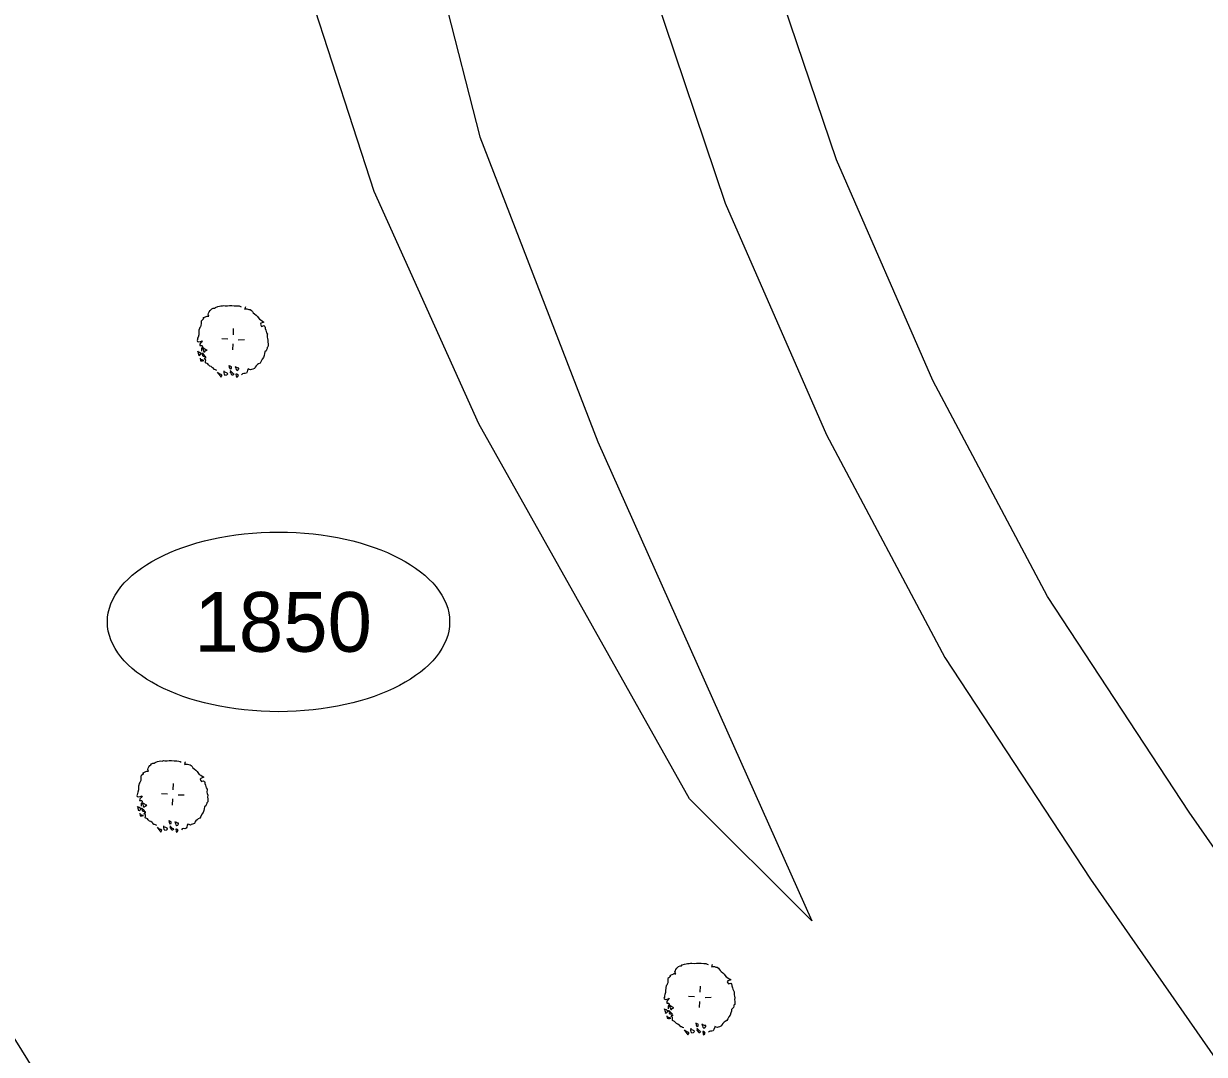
# Model space of a CAD drawing. Extents: x -601739 to -601442, y -1201912 to -1200862.
# Drawn here: x -601529.36 to -601489.81, y -1201669.33 to -1201634.81 of the extents above; entities that cross this region are included whole.
import ezdxf

# ---------------------------------------------------------------- set-up
doc = ezdxf.new("R2010")
doc.units = 0
for name, color, linetype in [('Hranice parcel', 7, 'Continuous'), ('Parcelní čísla', 7, 'Continuous'), ('u_dotčené parcely', 7, 'Continuous'), ('u_vysadba', 7, 'Continuous'), ('Vnitřní kresba', 7, 'Continuous')]:
    doc.layers.add(name, color=color, linetype=linetype)

msp = doc.modelspace()

# ---------------------------------------------------------------- linework, layer by layer
at = {"layer": 'Hranice parcel'}
for points in [[(-601518.5, -1201574.62), (-601510.22, -1201581.07), (-601510.94, -1201612.53), (-601510.72, -1201619.53), (-601510.05, -1201624.75), (-601508.24, -1201633.75), (-601505.86, -1201640.82), (-601502.47, -1201648.58), (-601498.5, -1201656.04), (-601493.62, -1201663.46), (-601488.75, -1201670.45), (-601479.72, -1201682.69), (-601465.426, -1201700.638)], [(-601505.676, -1201700.638), (-601519.73, -1201684.8), (-601540.64, -1201651.14), (-601563.05, -1201608.38), (-601567.44, -1201599.25)], [(-601460.43, -1201700.48), (-601476.54, -1201680.26), (-601485.5, -1201668.12), (-601490.31, -1201661.22), (-601495.06, -1201653.99), (-601498.9, -1201646.76), (-601502.13, -1201639.37), (-601504.35, -1201632.81), (-601505.66, -1201626.3)]]:
    msp.add_lwpolyline(points, dxfattribs=at)
at = {"layer": 'u_dotčené parcely'}
msp.add_ellipse((-601520.821, -1201654.846), major_axis=(-5.732, 0), ratio=0.524694, dxfattribs=at)
at = {"layer": 'u_vysadba'}
for points in [[(-601523.335, -1201644.685), (-601523.333, -1201644.656), (-601523.273, -1201644.63), (-601523.243, -1201644.617), (-601523.213, -1201644.604), (-601523.184, -1201644.605), (-601523.155, -1201644.607), (-601523.168, -1201644.577), (-601523.181, -1201644.547), (-601523.164, -1201644.504), (-601523.147, -1201644.461), (-601523.116, -1201644.418), (-601523.085, -1201644.391), (-601523.054, -1201644.363), (-601523.009, -1201644.336), (-601522.965, -1201644.338), (-601522.934, -1201644.311), (-601522.86, -1201644.285), (-601522.801, -1201644.274), (-601522.756, -1201644.262), (-601522.698, -1201644.265), (-601522.653, -1201644.252), (-601522.609, -1201644.255), (-601522.536, -1201644.259), (-601522.463, -1201644.248), (-601522.39, -1201644.252), (-601522.302, -1201644.256), (-601522.214, -1201644.261), (-601522.141, -1201644.265), (-601522.098, -1201644.282), (-601522.07, -1201644.298)], [(-601521.923, -1201644.291), (-601521.939, -1201644.319), (-601521.941, -1201644.349), (-601521.957, -1201644.377), (-601521.912, -1201644.365), (-601521.883, -1201644.366), (-601521.854, -1201644.368), (-601521.811, -1201644.385), (-601521.767, -1201644.387), (-601521.725, -1201644.419), (-601521.697, -1201644.449), (-601521.67, -1201644.495), (-601521.628, -1201644.526), (-601521.572, -1201644.573), (-601521.53, -1201644.619), (-601521.503, -1201644.65), (-601521.462, -1201644.711), (-601521.405, -1201644.743), (-601521.363, -1201644.775), (-601521.32, -1201644.791), (-601521.321, -1201644.821)], [(-601523.335, -1201644.685), (-601523.336, -1201644.7), (-601523.382, -1201644.741), (-601523.413, -1201644.769), (-601523.415, -1201644.813), (-601523.417, -1201644.856), (-601523.42, -1201644.915), (-601523.437, -1201644.958), (-601523.453, -1201644.986), (-601523.469, -1201645.015), (-601523.487, -1201645.072), (-601523.489, -1201645.102), (-601523.492, -1201645.16), (-601523.494, -1201645.204), (-601523.496, -1201645.233), (-601523.514, -1201645.305), (-601523.531, -1201645.348), (-601523.533, -1201645.392), (-601523.549, -1201645.42), (-601523.536, -1201645.45), (-601523.493, -1201645.467), (-601523.404, -1201645.443), (-601523.374, -1201645.43), (-601523.407, -1201645.487), (-601523.437, -1201645.514), (-601523.453, -1201645.543), (-601523.456, -1201645.586), (-601523.427, -1201645.588), (-601523.383, -1201645.59), (-601523.37, -1201645.62), (-601523.387, -1201645.663), (-601523.403, -1201645.692), (-601523.405, -1201645.736), (-601523.407, -1201645.779)], [(-601521.321, -1201644.821), (-601521.366, -1201644.833), (-601521.411, -1201644.845), (-601521.427, -1201644.874), (-601521.414, -1201644.904), (-601521.387, -1201644.949), (-601521.357, -1201644.936), (-601521.312, -1201644.924), (-601521.284, -1201644.954), (-601521.271, -1201644.984), (-601521.273, -1201645.014), (-601521.247, -1201645.074), (-601521.235, -1201645.118), (-601521.222, -1201645.163), (-601521.195, -1201645.208), (-601521.197, -1201645.237), (-601521.199, -1201645.281), (-601521.201, -1201645.31), (-601521.189, -1201645.355), (-601521.177, -1201645.414), (-601521.18, -1201645.472), (-601521.169, -1201645.532), (-601521.17, -1201645.561), (-601521.172, -1201645.59), (-601521.174, -1201645.634), (-601521.205, -1201645.661), (-601521.206, -1201645.691), (-601521.223, -1201645.734), (-601521.239, -1201645.762), (-601521.285, -1201645.804), (-601521.289, -1201645.862), (-601521.306, -1201645.92), (-601521.325, -1201645.992), (-601521.372, -1201646.048), (-601521.405, -1201646.119), (-601521.437, -1201646.176), (-601521.497, -1201646.202), (-601521.528, -1201646.23), (-601521.574, -1201646.272), (-601521.605, -1201646.314), (-601521.622, -1201646.357), (-601521.682, -1201646.383), (-601521.727, -1201646.395), (-601521.757, -1201646.408), (-601521.8, -1201646.391), (-601521.843, -1201646.375), (-601521.86, -1201646.418), (-601521.877, -1201646.475), (-601521.894, -1201646.518), (-601521.939, -1201646.531), (-601521.983, -1201646.528)], [(-601522.335, -1201645.227), (-601522.325, -1201645.022)], [(-601523.357, -1201645.65), (-601523.359, -1201645.694), (-601523.346, -1201645.724), (-601523.334, -1201645.769), (-601523.32, -1201645.799), (-601523.291, -1201645.8), (-601523.275, -1201645.772), (-601523.215, -1201645.746), (-601523.258, -1201645.729), (-601523.287, -1201645.713), (-601523.344, -1201645.68)], [(-601522.519, -1201645.378), (-601522.724, -1201645.367)], [(-601522.352, -1201645.533), (-601522.362, -1201645.738)], [(-601522.169, -1201645.396), (-601521.963, -1201645.393)], [(-601523.539, -1201645.772), (-601523.526, -1201645.802), (-601523.513, -1201645.847), (-601523.5, -1201645.877), (-601523.502, -1201645.906), (-601523.473, -1201645.922), (-601523.443, -1201645.895), (-601523.397, -1201645.853), (-601523.426, -1201645.852), (-601523.468, -1201645.82), (-601523.511, -1201645.803)], [(-601523.449, -1201646.011), (-601523.439, -1201646.1), (-601523.395, -1201646.102), (-601523.366, -1201646.104), (-601523.321, -1201646.091), (-601523.379, -1201646.074), (-601523.423, -1201646.071), (-601523.436, -1201646.041)], [(-601523.381, -1201645.839), (-601523.34, -1201645.885), (-601523.298, -1201645.932), (-601523.256, -1201645.963)], [(-601523.256, -1201645.963), (-601523.285, -1201645.962), (-601523.314, -1201645.96), (-601523.344, -1201645.958), (-601523.357, -1201645.929), (-601523.355, -1201645.899), (-601523.368, -1201645.869)], [(-601522.885, -1201646.422), (-601522.928, -1201646.405), (-601522.956, -1201646.389), (-601522.986, -1201646.387), (-601523.012, -1201646.342), (-601523.041, -1201646.326), (-601523.083, -1201646.294), (-601523.126, -1201646.277), (-601523.168, -1201646.231), (-601523.195, -1201646.201), (-601523.267, -1201646.168), (-601523.264, -1201646.124), (-601523.262, -1201646.08), (-601523.275, -1201646.05), (-601523.304, -1201646.034), (-601523.272, -1201645.992), (-601523.243, -1201645.993)], [(-601522.873, -1201646.481), (-601522.777, -1201646.603), (-601522.75, -1201646.649), (-601522.719, -1201646.606), (-601522.717, -1201646.577), (-601522.746, -1201646.561), (-601522.789, -1201646.544), (-601522.817, -1201646.528), (-601522.846, -1201646.512)], [(-601522.651, -1201646.434), (-601522.655, -1201646.507), (-601522.643, -1201646.552), (-601522.615, -1201646.583), (-601522.556, -1201646.571), (-601522.525, -1201646.543), (-601522.538, -1201646.514), (-601522.581, -1201646.497), (-601522.624, -1201646.48)], [(-601522.481, -1201646.253), (-601522.47, -1201646.327), (-601522.443, -1201646.372), (-601522.398, -1201646.36), (-601522.397, -1201646.331), (-601522.395, -1201646.301), (-601522.438, -1201646.285), (-601522.467, -1201646.268)], [(-601522.446, -1201646.431), (-601522.362, -1201646.508), (-601522.334, -1201646.524), (-601522.321, -1201646.554), (-601522.352, -1201646.582), (-601522.381, -1201646.58), (-601522.394, -1201646.55), (-601522.421, -1201646.505), (-601522.448, -1201646.474)], [(-601522.278, -1201646.293), (-601522.252, -1201646.353), (-601522.239, -1201646.398), (-601522.212, -1201646.428), (-601522.182, -1201646.415), (-601522.15, -1201646.373), (-601522.149, -1201646.344), (-601522.192, -1201646.341), (-601522.221, -1201646.325), (-601522.249, -1201646.309), (-601522.278, -1201646.308)], [(-601522.247, -1201646.544), (-601522.236, -1201646.617), (-601522.223, -1201646.647), (-601522.193, -1201646.634), (-601522.162, -1201646.592), (-601522.189, -1201646.561), (-601522.218, -1201646.545), (-601522.247, -1201646.544)], [(-601521.983, -1201646.528), (-601522.027, -1201646.541), (-601522.058, -1201646.568)], [(-601525.353, -1201659.926), (-601525.352, -1201659.897), (-601525.292, -1201659.871), (-601525.262, -1201659.858), (-601525.232, -1201659.845), (-601525.203, -1201659.847), (-601525.173, -1201659.848), (-601525.186, -1201659.818), (-601525.199, -1201659.788), (-601525.183, -1201659.745), (-601525.166, -1201659.702), (-601525.134, -1201659.66), (-601525.103, -1201659.632), (-601525.073, -1201659.605), (-601525.027, -1201659.578), (-601524.983, -1201659.58), (-601524.953, -1201659.552), (-601524.878, -1201659.527), (-601524.819, -1201659.515), (-601524.774, -1201659.503), (-601524.716, -1201659.506), (-601524.671, -1201659.494), (-601524.628, -1201659.496), (-601524.555, -1201659.5), (-601524.481, -1201659.489), (-601524.408, -1201659.493), (-601524.32, -1201659.498), (-601524.233, -1201659.502), (-601524.16, -1201659.506), (-601524.117, -1201659.523), (-601524.088, -1201659.539)], [(-601523.941, -1201659.532), (-601523.957, -1201659.561), (-601523.959, -1201659.59), (-601523.975, -1201659.619), (-601523.931, -1201659.606), (-601523.901, -1201659.608), (-601523.872, -1201659.609), (-601523.829, -1201659.626), (-601523.785, -1201659.629), (-601523.743, -1201659.66), (-601523.715, -1201659.691), (-601523.688, -1201659.736), (-601523.646, -1201659.768), (-601523.59, -1201659.815), (-601523.549, -1201659.861), (-601523.521, -1201659.891), (-601523.48, -1201659.952), (-601523.423, -1201659.984), (-601523.381, -1201660.016), (-601523.338, -1201660.033), (-601523.34, -1201660.062)], [(-601525.353, -1201659.926), (-601525.354, -1201659.941), (-601525.4, -1201659.983), (-601525.431, -1201660.01), (-601525.433, -1201660.054), (-601525.435, -1201660.098), (-601525.439, -1201660.156), (-601525.455, -1201660.199), (-601525.472, -1201660.228), (-601525.488, -1201660.256), (-601525.505, -1201660.314), (-601525.507, -1201660.343), (-601525.51, -1201660.401), (-601525.512, -1201660.445), (-601525.514, -1201660.474), (-601525.532, -1201660.547), (-601525.549, -1201660.59), (-601525.552, -1201660.633), (-601525.568, -1201660.662), (-601525.555, -1201660.692), (-601525.512, -1201660.709), (-601525.422, -1201660.684), (-601525.393, -1201660.671), (-601525.425, -1201660.728), (-601525.456, -1201660.756), (-601525.472, -1201660.784), (-601525.474, -1201660.828), (-601525.445, -1201660.829), (-601525.401, -1201660.832), (-601525.388, -1201660.862), (-601525.405, -1201660.905), (-601525.421, -1201660.933), (-601525.423, -1201660.977), (-601525.426, -1201661.021)], [(-601524.354, -1201660.468), (-601524.343, -1201660.264)], [(-601523.34, -1201660.062), (-601523.384, -1201660.074), (-601523.429, -1201660.087), (-601523.445, -1201660.115), (-601523.432, -1201660.145), (-601523.405, -1201660.19), (-601523.375, -1201660.177), (-601523.33, -1201660.165), (-601523.303, -1201660.196), (-601523.29, -1201660.226), (-601523.291, -1201660.255), (-601523.265, -1201660.315), (-601523.253, -1201660.36), (-601523.241, -1201660.404), (-601523.214, -1201660.449), (-601523.215, -1201660.479), (-601523.218, -1201660.522), (-601523.219, -1201660.552), (-601523.207, -1201660.596), (-601523.195, -1201660.655), (-601523.198, -1201660.714), (-601523.187, -1201660.773), (-601523.188, -1201660.802), (-601523.19, -1201660.831), (-601523.192, -1201660.875), (-601523.223, -1201660.903), (-601523.225, -1201660.932), (-601523.241, -1201660.975), (-601523.258, -1201661.004), (-601523.304, -1201661.045), (-601523.307, -1201661.103), (-601523.324, -1201661.161), (-601523.343, -1201661.233), (-601523.39, -1201661.289), (-601523.423, -1201661.361), (-601523.455, -1201661.418), (-601523.515, -1201661.444), (-601523.546, -1201661.472), (-601523.592, -1201661.513), (-601523.624, -1201661.555), (-601523.64, -1201661.598), (-601523.7, -1201661.624), (-601523.745, -1201661.637), (-601523.775, -1201661.65), (-601523.818, -1201661.633), (-601523.861, -1201661.616), (-601523.878, -1201661.659), (-601523.896, -1201661.717), (-601523.913, -1201661.76), (-601523.957, -1201661.772), (-601524.001, -1201661.77)], [(-601524.537, -1201660.619), (-601524.742, -1201660.609)], [(-601524.187, -1201660.638), (-601523.982, -1201660.634)], [(-601525.557, -1201661.014), (-601525.544, -1201661.044), (-601525.532, -1201661.088), (-601525.519, -1201661.118), (-601525.52, -1201661.148), (-601525.492, -1201661.164), (-601525.461, -1201661.136), (-601525.415, -1201661.095), (-601525.444, -1201661.093), (-601525.486, -1201661.062), (-601525.529, -1201661.045)], [(-601525.4, -1201661.081), (-601525.358, -1201661.127), (-601525.317, -1201661.173), (-601525.274, -1201661.205)], [(-601525.274, -1201661.205), (-601525.303, -1201661.203), (-601525.333, -1201661.201), (-601525.362, -1201661.2), (-601525.375, -1201661.17), (-601525.373, -1201661.141), (-601525.386, -1201661.111)], [(-601525.375, -1201660.892), (-601525.377, -1201660.936), (-601525.364, -1201660.966), (-601525.352, -1201661.01), (-601525.339, -1201661.04), (-601525.31, -1201661.042), (-601525.293, -1201661.013), (-601525.233, -1201660.987), (-601525.277, -1201660.97), (-601525.305, -1201660.954), (-601525.362, -1201660.922)], [(-601524.37, -1201660.775), (-601524.381, -1201660.979)], [(-601525.467, -1201661.253), (-601525.457, -1201661.341), (-601525.413, -1201661.344), (-601525.384, -1201661.345), (-601525.34, -1201661.333), (-601525.397, -1201661.315), (-601525.441, -1201661.313), (-601525.454, -1201661.283)], [(-601524.903, -1201661.663), (-601524.946, -1201661.647), (-601524.975, -1201661.63), (-601525.004, -1201661.629), (-601525.031, -1201661.583), (-601525.059, -1201661.567), (-601525.101, -1201661.536), (-601525.144, -1201661.519), (-601525.186, -1201661.473), (-601525.214, -1201661.442), (-601525.285, -1201661.409), (-601525.283, -1201661.365), (-601525.28, -1201661.321), (-601525.293, -1201661.291), (-601525.322, -1201661.275), (-601525.29, -1201661.233), (-601525.261, -1201661.235)], [(-601524.499, -1201661.494), (-601524.488, -1201661.568), (-601524.461, -1201661.614), (-601524.417, -1201661.601), (-601524.415, -1201661.572), (-601524.414, -1201661.543), (-601524.457, -1201661.526), (-601524.485, -1201661.51)], [(-601524.296, -1201661.534), (-601524.27, -1201661.594), (-601524.258, -1201661.639), (-601524.23, -1201661.67), (-601524.2, -1201661.657), (-601524.168, -1201661.614), (-601524.167, -1201661.585), (-601524.211, -1201661.583), (-601524.239, -1201661.567), (-601524.268, -1201661.551), (-601524.297, -1201661.549)], [(-601524.892, -1201661.723), (-601524.796, -1201661.845), (-601524.769, -1201661.89), (-601524.737, -1201661.848), (-601524.736, -1201661.819), (-601524.764, -1201661.803), (-601524.807, -1201661.786), (-601524.836, -1201661.769), (-601524.864, -1201661.753)], [(-601524.67, -1201661.676), (-601524.673, -1201661.749), (-601524.661, -1201661.793), (-601524.633, -1201661.824), (-601524.574, -1201661.813), (-601524.544, -1201661.785), (-601524.557, -1201661.755), (-601524.6, -1201661.738), (-601524.643, -1201661.721)], [(-601524.464, -1201661.672), (-601524.381, -1201661.75), (-601524.352, -1201661.766), (-601524.339, -1201661.796), (-601524.37, -1201661.823), (-601524.399, -1201661.822), (-601524.412, -1201661.792), (-601524.439, -1201661.747), (-601524.467, -1201661.716)], [(-601524.265, -1201661.785), (-601524.255, -1201661.859), (-601524.241, -1201661.889), (-601524.212, -1201661.876), (-601524.18, -1201661.833), (-601524.208, -1201661.803), (-601524.236, -1201661.787), (-601524.265, -1201661.785)], [(-601524.001, -1201661.77), (-601524.046, -1201661.782), (-601524.076, -1201661.81)], [(-601507.697, -1201666.71), (-601507.696, -1201666.68), (-601507.636, -1201666.654), (-601507.606, -1201666.641), (-601507.576, -1201666.628), (-601507.546, -1201666.63), (-601507.517, -1201666.631), (-601507.53, -1201666.601), (-601507.543, -1201666.571), (-601507.526, -1201666.528), (-601507.51, -1201666.485), (-601507.478, -1201666.443), (-601507.447, -1201666.415), (-601507.417, -1201666.388), (-601507.371, -1201666.361), (-601507.327, -1201666.363), (-601507.297, -1201666.335), (-601507.222, -1201666.31), (-601507.163, -1201666.299), (-601507.118, -1201666.286), (-601507.06, -1201666.289), (-601507.015, -1201666.277), (-601506.972, -1201666.279), (-601506.899, -1201666.283), (-601506.825, -1201666.272), (-601506.752, -1201666.276), (-601506.664, -1201666.281), (-601506.577, -1201666.286), (-601506.504, -1201666.289), (-601506.46, -1201666.306), (-601506.432, -1201666.322)], [(-601506.285, -1201666.316), (-601506.301, -1201666.344), (-601506.303, -1201666.373), (-601506.319, -1201666.402), (-601506.275, -1201666.389), (-601506.245, -1201666.391), (-601506.216, -1201666.392), (-601506.173, -1201666.409), (-601506.129, -1201666.412), (-601506.087, -1201666.443), (-601506.059, -1201666.474), (-601506.032, -1201666.519), (-601505.99, -1201666.551), (-601505.934, -1201666.598), (-601505.893, -1201666.644), (-601505.865, -1201666.675), (-601505.824, -1201666.735), (-601505.767, -1201666.768), (-601505.725, -1201666.799), (-601505.682, -1201666.816), (-601505.684, -1201666.845)], [(-601507.697, -1201666.71), (-601507.698, -1201666.724), (-601507.744, -1201666.766), (-601507.775, -1201666.793), (-601507.777, -1201666.837), (-601507.779, -1201666.881), (-601507.782, -1201666.939), (-601507.799, -1201666.982), (-601507.816, -1201667.011), (-601507.832, -1201667.039), (-601507.849, -1201667.097), (-601507.851, -1201667.126), (-601507.854, -1201667.184), (-601507.856, -1201667.228), (-601507.858, -1201667.258), (-601507.876, -1201667.33), (-601507.893, -1201667.373), (-601507.896, -1201667.417), (-601507.912, -1201667.445), (-601507.899, -1201667.475), (-601507.856, -1201667.492), (-601507.766, -1201667.467), (-601507.736, -1201667.454), (-601507.769, -1201667.511), (-601507.8, -1201667.539), (-601507.816, -1201667.567), (-601507.818, -1201667.611), (-601507.789, -1201667.613), (-601507.745, -1201667.615), (-601507.732, -1201667.645), (-601507.749, -1201667.688), (-601507.765, -1201667.716), (-601507.767, -1201667.76), (-601507.77, -1201667.804)], [(-601506.698, -1201667.251), (-601506.687, -1201667.047)], [(-601505.684, -1201666.845), (-601505.728, -1201666.858), (-601505.773, -1201666.87), (-601505.789, -1201666.898), (-601505.776, -1201666.928), (-601505.749, -1201666.974), (-601505.719, -1201666.961), (-601505.674, -1201666.948), (-601505.647, -1201666.979), (-601505.634, -1201667.009), (-601505.635, -1201667.038), (-601505.609, -1201667.098), (-601505.597, -1201667.143), (-601505.585, -1201667.187), (-601505.558, -1201667.233), (-601505.559, -1201667.262), (-601505.561, -1201667.306), (-601505.563, -1201667.335), (-601505.551, -1201667.379), (-601505.539, -1201667.439), (-601505.542, -1201667.497), (-601505.531, -1201667.556), (-601505.532, -1201667.585), (-601505.534, -1201667.615), (-601505.536, -1201667.658), (-601505.567, -1201667.686), (-601505.568, -1201667.715), (-601505.585, -1201667.758), (-601505.602, -1201667.787), (-601505.648, -1201667.828), (-601505.651, -1201667.887), (-601505.668, -1201667.944), (-601505.687, -1201668.016), (-601505.734, -1201668.073), (-601505.767, -1201668.144), (-601505.799, -1201668.201), (-601505.859, -1201668.227), (-601505.89, -1201668.255), (-601505.936, -1201668.296), (-601505.967, -1201668.338), (-601505.984, -1201668.381), (-601506.044, -1201668.408), (-601506.089, -1201668.42), (-601506.119, -1201668.433), (-601506.162, -1201668.416), (-601506.205, -1201668.399), (-601506.222, -1201668.442), (-601506.24, -1201668.5), (-601506.256, -1201668.543), (-601506.301, -1201668.555), (-601506.345, -1201668.553)], [(-601506.881, -1201667.402), (-601507.086, -1201667.392)], [(-601506.531, -1201667.421), (-601506.326, -1201667.417)], [(-601507.901, -1201667.797), (-601507.888, -1201667.827), (-601507.876, -1201667.872), (-601507.863, -1201667.902), (-601507.864, -1201667.931), (-601507.836, -1201667.947), (-601507.805, -1201667.919), (-601507.759, -1201667.878), (-601507.788, -1201667.876), (-601507.83, -1201667.845), (-601507.873, -1201667.828)], [(-601507.743, -1201667.864), (-601507.702, -1201667.91), (-601507.66, -1201667.956), (-601507.618, -1201667.988)], [(-601507.719, -1201667.675), (-601507.721, -1201667.719), (-601507.708, -1201667.749), (-601507.696, -1201667.793), (-601507.683, -1201667.823), (-601507.654, -1201667.825), (-601507.637, -1201667.796), (-601507.577, -1201667.77), (-601507.62, -1201667.753), (-601507.649, -1201667.737), (-601507.706, -1201667.705)], [(-601506.714, -1201667.558), (-601506.725, -1201667.762)], [(-601507.811, -1201668.036), (-601507.801, -1201668.124), (-601507.757, -1201668.127), (-601507.728, -1201668.128), (-601507.684, -1201668.116), (-601507.741, -1201668.098), (-601507.785, -1201668.096), (-601507.798, -1201668.066)], [(-601507.618, -1201667.988), (-601507.647, -1201667.986), (-601507.677, -1201667.985), (-601507.706, -1201667.983), (-601507.719, -1201667.953), (-601507.717, -1201667.924), (-601507.73, -1201667.894)], [(-601507.247, -1201668.447), (-601507.29, -1201668.43), (-601507.319, -1201668.413), (-601507.348, -1201668.412), (-601507.375, -1201668.367), (-601507.403, -1201668.35), (-601507.445, -1201668.319), (-601507.488, -1201668.302), (-601507.53, -1201668.256), (-601507.558, -1201668.225), (-601507.629, -1201668.192), (-601507.627, -1201668.148), (-601507.624, -1201668.104), (-601507.637, -1201668.074), (-601507.666, -1201668.058), (-601507.634, -1201668.016), (-601507.605, -1201668.018)], [(-601506.843, -1201668.278), (-601506.832, -1201668.351), (-601506.805, -1201668.397), (-601506.761, -1201668.384), (-601506.759, -1201668.355), (-601506.758, -1201668.326), (-601506.801, -1201668.309), (-601506.829, -1201668.293)], [(-601507.236, -1201668.506), (-601507.14, -1201668.628), (-601507.113, -1201668.673), (-601507.081, -1201668.631), (-601507.08, -1201668.602), (-601507.108, -1201668.586), (-601507.151, -1201668.569), (-601507.18, -1201668.553), (-601507.208, -1201668.536)], [(-601507.013, -1201668.459), (-601507.017, -1201668.532), (-601507.005, -1201668.576), (-601506.977, -1201668.607), (-601506.918, -1201668.596), (-601506.887, -1201668.568), (-601506.901, -1201668.538), (-601506.944, -1201668.521), (-601506.987, -1201668.504)], [(-601506.808, -1201668.455), (-601506.725, -1201668.533), (-601506.696, -1201668.549), (-601506.683, -1201668.579), (-601506.714, -1201668.606), (-601506.743, -1201668.605), (-601506.756, -1201668.575), (-601506.783, -1201668.53), (-601506.811, -1201668.499)], [(-601506.64, -1201668.318), (-601506.614, -1201668.377), (-601506.602, -1201668.422), (-601506.574, -1201668.453), (-601506.544, -1201668.44), (-601506.512, -1201668.397), (-601506.511, -1201668.368), (-601506.555, -1201668.366), (-601506.583, -1201668.35), (-601506.612, -1201668.334), (-601506.641, -1201668.332)], [(-601506.609, -1201668.568), (-601506.599, -1201668.642), (-601506.585, -1201668.672), (-601506.555, -1201668.659), (-601506.524, -1201668.617), (-601506.552, -1201668.586), (-601506.58, -1201668.57), (-601506.609, -1201668.568)], [(-601506.345, -1201668.553), (-601506.389, -1201668.565), (-601506.42, -1201668.593)]]:
    msp.add_lwpolyline(points, dxfattribs=at)
at = {"layer": 'Vnitřní kresba'}
for p, q in [((-601517, -1201627.14), (-601514.08, -1201638.6)), ((-601517.62, -1201640.43), (-601520.26, -1201632.29)), ((-601514.08, -1201638.6), (-601510.13, -1201648.82)), ((-601514.11, -1201648.21), (-601517.62, -1201640.43)), ((-601507.05, -1201660.77), (-601514.11, -1201648.21)), ((-601510.13, -1201648.82), (-601502.96, -1201664.86)), ((-601502.96, -1201664.86), (-601507.05, -1201660.77))]:
    msp.add_line(p, q, dxfattribs=at)

# ---------------------------------------------------------------- texts
at = {"layer": 'Parcelní čísla'}
msp.add_text('1850', height=2, dxfattribs=at).set_placement((-601523.64, -1201655.846))

doc.saveas('drawing.dxf')
